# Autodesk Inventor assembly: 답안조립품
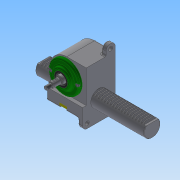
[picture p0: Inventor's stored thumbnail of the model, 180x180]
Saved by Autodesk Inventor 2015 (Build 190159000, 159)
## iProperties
Created: 2019-06
Part Number: 답안조립품
Document SubType Name: Assembly
Designer: user
Mass: 3231.44 g
Surface Area: 1361.79 cm^2
Volume: 644.408 cm^3
Density: 5.01459 g/cm^3
Author: user
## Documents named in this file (10)
- C:\Users\user\Desktop\390604V1008\답안조립품.iam
- C:\Users\user\Desktop\390604V1008\본체.ipt
- C:\Users\user\Desktop\390604V1008\래크.ipt
- C:\Users\user\Desktop\390604V1008\누름쇠.ipt
- C:\Users\user\Desktop\390604V1008\볼트 M4.ipt
- C:\Users\user\Desktop\390604V1008\앞커버.ipt
- C:\Users\user\Desktop\390604V1008\오일 실 17 30 5.ipt
- C:\Users\user\Desktop\390604V1008\뒤커버.ipt
- C:\Users\user\Desktop\390604V1008\피니언.ipt
- C:\Users\user\Desktop\390604V1008\베어링 6003.ipt
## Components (1 placed, 1 different names)
1. 피니언:1 — 구동조건
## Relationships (1: Angle 1)
- 구동조건 [Angle]: 피니언:1
